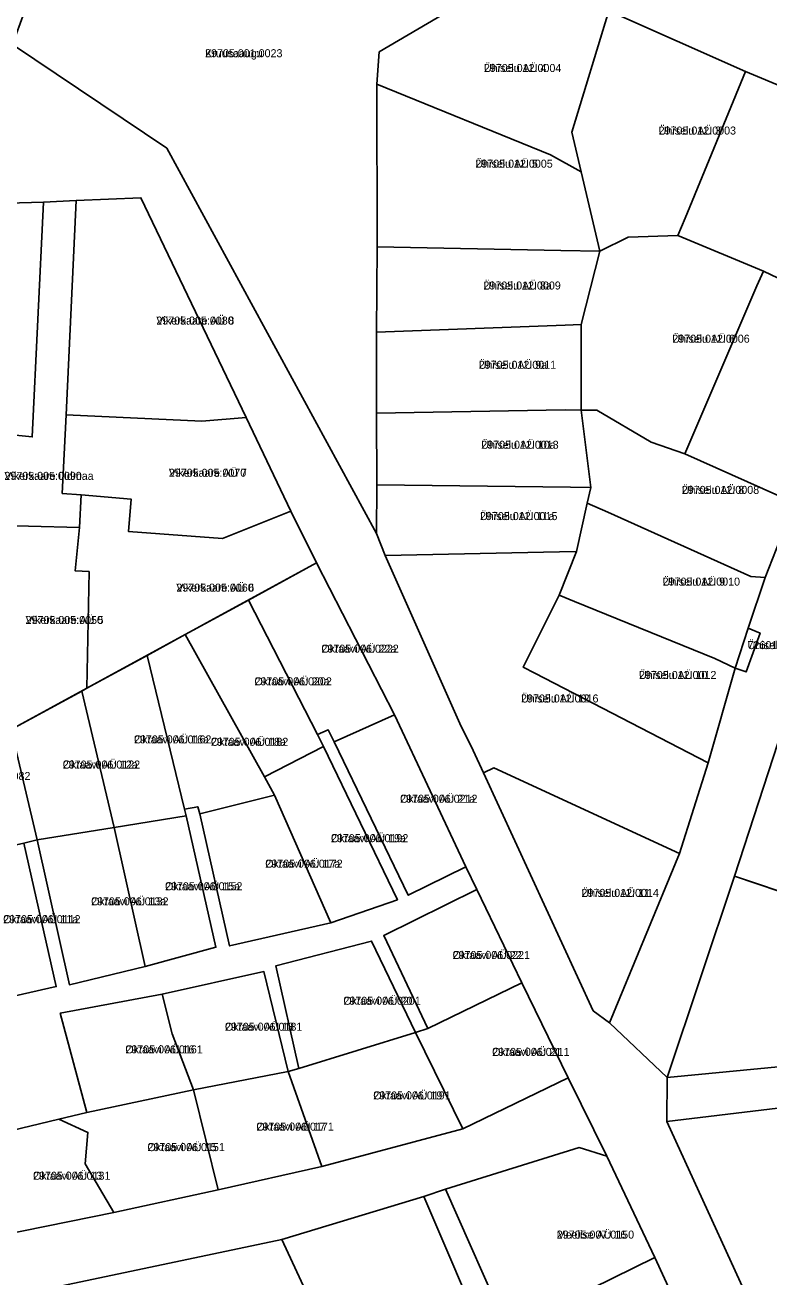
# Model space of a CAD drawing. Extents: x 504287 to 537970, y 6539941 to 6586214.
# Drawn here: x 519134.4 to 519273.8, y 6563201.2 to 6563435.8 of the extents above; entities that cross this region are included whole.
import ezdxf

# ---------------------------------------------------------------- set-up
doc = ezdxf.new("R2010")
doc.units = 0
for name, color, linetype in [('L_AADRESS', 7, 'Continuous'), ('PIIR', 7, 'Continuous'), ('TUNNUS', 7, 'Continuous')]:
    doc.layers.add(name, color=color, linetype=linetype)

msp = doc.modelspace()

# ---------------------------------------------------------------- linework, layer by layer
at = {"layer": 'PIIR'}
for points in [[(519140.05, 6563476.97), (519153.68, 6563480.42), (519218.45, 6563486.02), (519326.38, 6563519.01), (519226.15, 6563445.74), (519200.78, 6563430.75), (519200.34, 6563424.73), (519200.43, 6563394.25), (519200.26, 6563378.22), (519200.3, 6563363.09), (519200.34, 6563349.64), (519200.31, 6563340.52), (519160.99, 6563412.72), (519132.07, 6563432.14), (519134.26, 6563438.15), (519138.11, 6563452.64)], [(519350.47, 6563485.2), (519381, 6563460.99), (519434.83, 6563428.79), (519416.35, 6563420.15), (519412.28, 6563418.89), (519380.79, 6563408.69), (519350.37, 6563399.28), (519345.34, 6563397.59), (519329.1, 6563391.84), (519322.55, 6563399.61), (519317.71, 6563405.41), (519293.21, 6563417.16), (519269.41, 6563427.1), (519243.82, 6563438.48), (519226.15, 6563445.74), (519326.38, 6563519.01)], [(519226.15, 6563445.74), (519241.86, 6563439.37), (519243.82, 6563438.48), (519236.91, 6563415.74), (519238.66, 6563408.27), (519232.9, 6563411.48), (519200.34, 6563424.73), (519200.78, 6563430.75)], [(519243.82, 6563438.48), (519269.41, 6563427.1), (519258.11, 6563399.62), (519256.76, 6563396.34), (519247.47, 6563396.06), (519242.12, 6563393.41), (519238.66, 6563408.27), (519236.91, 6563415.74)], [(519269.41, 6563427.1), (519293.21, 6563417.16), (519281.99, 6563388.88), (519280.8, 6563385.86), (519272.83, 6563389.69), (519256.76, 6563396.34), (519258.11, 6563399.62)], [(519200.34, 6563424.73), (519232.9, 6563411.48), (519238.66, 6563408.27), (519242.12, 6563393.41), (519234.84, 6563393.56), (519200.43, 6563394.25)], [(519116.74, 6563364.03), (519113.68, 6563364.22), (519114.8, 6563373.92), (519100.63, 6563375.97), (519128.79, 6563402.34), (519137.88, 6563402.61), (519135.78, 6563358.63), (519118.22, 6563360.41)], [(519116.13, 6563342.47), (519116.63, 6563346.75), (519118.22, 6563360.41), (519135.78, 6563358.63), (519137.88, 6563402.61), (519144.03, 6563402.9), (519142.15, 6563362.74), (519141.4, 6563348.02), (519144.96, 6563347.74), (519144.6, 6563341.63), (519125.43, 6563342.12)], [(519144.03, 6563402.9), (519156.12, 6563403.42), (519175.89, 6563362.25), (519167.56, 6563361.55), (519142.15, 6563362.74)], [(519243.96, 6563248.8), (519257.06, 6563280.53), (519262.44, 6563297.56), (519267.48, 6563315.28), (519269.57, 6563314.59), (519272.18, 6563321.86), (519269.95, 6563322.75), (519273.12, 6563332.24), (519278.63, 6563346.24), (519294.26, 6563375.39), (519296.93, 6563378.08), (519299.61, 6563380.78), (519322.55, 6563399.61), (519329.1, 6563391.84), (519318.65, 6563382.18), (519307.91, 6563372.29), (519305.41, 6563369.96), (519294.2, 6563350.93), (519291.63, 6563346.35), (519288.21, 6563340.08), (519278.22, 6563309.66), (519267.39, 6563276.29), (519254.76, 6563238.59)], [(519242.12, 6563393.41), (519247.47, 6563396.06), (519256.76, 6563396.34), (519272.83, 6563389.69), (519271.59, 6563386.95), (519258.09, 6563355.42), (519251.76, 6563357.61), (519241.56, 6563363.61), (519238.62, 6563363.64), (519238.64, 6563379.67)], [(519200.43, 6563394.25), (519234.84, 6563393.56), (519242.12, 6563393.41), (519238.64, 6563379.67), (519235.64, 6563379.56), (519200.26, 6563378.22)], [(519272.83, 6563389.69), (519280.8, 6563385.86), (519296.93, 6563378.08), (519294.26, 6563375.39), (519278.63, 6563346.24), (519258.09, 6563355.42), (519271.59, 6563386.95)], [(519200.26, 6563378.22), (519235.64, 6563379.56), (519238.64, 6563379.67), (519238.62, 6563363.64), (519235.67, 6563363.68), (519200.3, 6563363.09)], [(519154.28, 6563346.97), (519144.96, 6563347.74), (519141.4, 6563348.02), (519142.15, 6563362.74), (519167.56, 6563361.55), (519175.89, 6563362.25), (519184.24, 6563344.73), (519171.4, 6563339.55), (519153.79, 6563340.9)], [(519200.3, 6563363.09), (519235.67, 6563363.68), (519238.62, 6563363.64), (519240.44, 6563349.13), (519236.65, 6563349.18), (519200.34, 6563349.64)], [(519238.62, 6563363.64), (519241.56, 6563363.61), (519251.76, 6563357.61), (519258.09, 6563355.42), (519278.63, 6563346.24), (519273.12, 6563332.24), (519270.45, 6563332.44), (519243.61, 6563344.49), (519239.78, 6563346.21), (519240.44, 6563349.13)], [(519146.43, 6563333.37), (519143.81, 6563333.54), (519144.6, 6563341.63), (519144.96, 6563347.74), (519154.28, 6563346.97), (519153.79, 6563340.9), (519171.4, 6563339.55), (519184.24, 6563344.73), (519189.04, 6563335.01), (519146.02, 6563311.51)], [(519200.34, 6563349.64), (519236.65, 6563349.18), (519240.44, 6563349.13), (519239.78, 6563346.21), (519237.75, 6563337.17), (519234.58, 6563337.1), (519201.92, 6563336.41), (519200.31, 6563340.52)], [(519239.78, 6563346.21), (519243.61, 6563344.49), (519270.45, 6563332.44), (519273.12, 6563332.24), (519269.95, 6563322.75), (519267.48, 6563315.28), (519263.7, 6563317.11), (519237.42, 6563327.76), (519234.49, 6563328.95), (519237.75, 6563337.17)], [(519122.62, 6563308.55), (519125.43, 6563342.12), (519144.6, 6563341.63), (519143.81, 6563333.54), (519146.43, 6563333.37), (519146.02, 6563311.51), (519131.85, 6563303.77)], [(519201.92, 6563336.41), (519234.58, 6563337.1), (519237.75, 6563337.17), (519234.49, 6563328.95), (519227.8, 6563315.45), (519229.95, 6563314.34), (519262.44, 6563297.56), (519257.06, 6563280.53), (519222.29, 6563296.59), (519220.33, 6563295.68), (519218.38, 6563299.83), (519215.93, 6563304.93)], [(519189.04, 6563335.01), (519203.64, 6563306.54), (519192.38, 6563301.49), (519191.24, 6563303.72), (519189.23, 6563302.82), (519176.29, 6563328.04)], [(519234.49, 6563328.95), (519237.42, 6563327.76), (519263.7, 6563317.11), (519267.48, 6563315.28), (519262.44, 6563297.56), (519229.95, 6563314.34), (519227.8, 6563315.45)], [(519176.29, 6563328.04), (519189.23, 6563302.82), (519190.38, 6563300.59), (519179.29, 6563294.91), (519164.45, 6563321.58)], [(519267.48, 6563315.28), (519269.95, 6563322.75), (519272.18, 6563321.86), (519269.57, 6563314.59)], [(519166.79, 6563289.32), (519164.28, 6563288.84), (519157.29, 6563317.67), (519164.45, 6563321.58), (519179.29, 6563294.91), (519181.2, 6563291.47), (519167.18, 6563287.98)], [(519145.06, 6563310.99), (519146.02, 6563311.51), (519157.29, 6563317.67), (519164.28, 6563288.84), (519164.62, 6563287.6), (519151.13, 6563285.44)], [(519131.85, 6563303.77), (519145.06, 6563310.99), (519151.13, 6563285.44), (519136.69, 6563283.13)], [(519121.14, 6563309.32), (519122.62, 6563308.55), (519131.85, 6563303.77), (519136.69, 6563283.13), (519134.19, 6563282.46), (519120.36, 6563279.43), (519105.18, 6563291.09)], [(519314.69, 6563297.36), (519307.34, 6563281.57), (519292.55, 6563267.85), (519267.39, 6563276.29), (519278.22, 6563309.66)], [(519203.64, 6563306.54), (519217.05, 6563278.05), (519206.23, 6563272.72), (519192.38, 6563301.49)], [(519181.2, 6563291.47), (519179.29, 6563294.91), (519190.38, 6563300.59), (519204.2, 6563271.88), (519191.7, 6563267.57)], [(519220.33, 6563295.68), (519222.29, 6563296.59), (519257.06, 6563280.53), (519243.96, 6563248.8), (519240.88, 6563251.08)], [(519167.18, 6563287.98), (519181.2, 6563291.47), (519191.7, 6563267.57), (519172.75, 6563263.22)], [(519151.13, 6563285.44), (519164.62, 6563287.6), (519170.18, 6563262.97), (519156.94, 6563259.34)], [(519136.69, 6563283.13), (519151.13, 6563285.44), (519156.94, 6563259.34), (519142.74, 6563255.94)], [(519120.36, 6563279.43), (519134.19, 6563282.46), (519140.28, 6563255.61), (519126.2, 6563252.44)], [(519267.39, 6563276.29), (519292.51, 6563267.78), (519299.01, 6563242.84), (519254.76, 6563238.59)], [(519201.65, 6563265.15), (519219.07, 6563273.77), (519227.54, 6563256.3), (519209.93, 6563247.77)], [(519181.43, 6563259.52), (519199.36, 6563264.14), (519207.57, 6563247), (519185.76, 6563240.25)], [(519162.01, 6563246.75), (519160.12, 6563254.19), (519179.2, 6563258.42), (519183.74, 6563239.71), (519166.02, 6563236.24)], [(519207.57, 6563247), (519209.93, 6563247.77), (519227.54, 6563256.3), (519236.2, 6563238.48), (519216.47, 6563228.93)], [(519141.01, 6563250.64), (519160.12, 6563254.19), (519162.01, 6563246.75), (519166.02, 6563236.24), (519145.99, 6563231.98)], [(519183.74, 6563239.71), (519185.76, 6563240.25), (519207.57, 6563247), (519216.47, 6563228.93), (519190.06, 6563221.91)], [(519166.02, 6563236.24), (519183.74, 6563239.71), (519190.06, 6563221.91), (519170.59, 6563217.51)], [(519236.2, 6563238.48), (519243.47, 6563223.81), (519238.26, 6563225.44), (519213.24, 6563217.67), (519209.13, 6563216.28), (519182.57, 6563208.19), (519141.33, 6563199.52), (519136.15, 6563198.16), (519102.94, 6563190.91), (519097.15, 6563189.57), (519075.1, 6563172.56), (519071.2, 6563169.74), (519047.83, 6563153.98), (519019.15, 6563136.44), (519010.92, 6563141.43), (519070.28, 6563181.56), (519092.24, 6563203.65), (519125.45, 6563208.08), (519151.08, 6563213.3), (519170.59, 6563217.51), (519190.06, 6563221.91), (519216.47, 6563228.93)], [(519145.7, 6563222.39), (519146.21, 6563228.27), (519140.76, 6563230.74), (519145.99, 6563231.98), (519166.02, 6563236.24), (519170.59, 6563217.51), (519151.08, 6563213.3)], [(519293.15, 6563234.92), (519298.22, 6563198.28), (519274.24, 6563187.6), (519254.72, 6563230.35)], [(519123.65, 6563226.94), (519130.13, 6563228.2), (519140.76, 6563230.74), (519146.21, 6563228.27), (519145.7, 6563222.39), (519151.08, 6563213.3), (519125.45, 6563208.08)], [(519213.24, 6563217.67), (519238.26, 6563225.44), (519243.47, 6563223.81), (519252.43, 6563204.86), (519224.92, 6563191.31)], [(519188.58, 6563195.18), (519182.57, 6563208.19), (519209.13, 6563216.28), (519221.29, 6563187.94), (519197.09, 6563176.65)], [(519195.93, 6563150.95), (519193.44, 6563158.03), (519188.13, 6563172.69), (519197.09, 6563176.65), (519221.29, 6563187.94), (519209.13, 6563216.28), (519213.24, 6563217.67), (519224.92, 6563191.31), (519233.88, 6563168.84), (519205.14, 6563155.29)], [(519142.12, 6563196.85), (519141.33, 6563199.52), (519182.57, 6563208.19), (519188.58, 6563195.18), (519151.01, 6563177.45)], [(519224.92, 6563191.31), (519252.43, 6563204.86), (519262.87, 6563182.15), (519233.88, 6563168.84)]]:
    msp.add_lwpolyline(points, close=True, dxfattribs=at)
for points in [[(519132.07, 6563432.14), (519160.99, 6563412.72), (519200.31, 6563340.52), (519201.92, 6563336.41), (519215.93, 6563304.93), (519218.38, 6563299.83), (519220.33, 6563295.68), (519240.88, 6563251.08), (519243.96, 6563248.8), (519254.76, 6563238.59), (519254.72, 6563230.35), (519274.24, 6563187.6)], [(519262.87, 6563182.15), (519252.43, 6563204.86), (519243.47, 6563223.81), (519236.2, 6563238.48), (519227.54, 6563256.3), (519219.07, 6563273.77), (519217.05, 6563278.05), (519203.64, 6563306.54), (519189.04, 6563335.01), (519184.24, 6563344.73), (519175.89, 6563362.25), (519156.12, 6563403.42), (519144.03, 6563402.9), (519137.88, 6563402.61), (519128.79, 6563402.34)], [(519126.2, 6563252.44), (519140.28, 6563255.61), (519134.19, 6563282.46), (519136.69, 6563283.13), (519142.74, 6563255.94), (519156.94, 6563259.34), (519170.18, 6563262.97), (519164.62, 6563287.6), (519164.28, 6563288.84), (519166.79, 6563289.32), (519167.18, 6563287.98), (519172.75, 6563263.22), (519191.7, 6563267.57), (519204.2, 6563271.88), (519190.38, 6563300.59), (519189.23, 6563302.82), (519191.24, 6563303.72), (519192.38, 6563301.49), (519206.23, 6563272.72), (519217.05, 6563278.05), (519219.07, 6563273.77), (519201.65, 6563265.15), (519209.93, 6563247.77), (519207.57, 6563247), (519199.36, 6563264.14), (519181.43, 6563259.52), (519185.76, 6563240.25), (519183.74, 6563239.71), (519179.2, 6563258.42), (519160.12, 6563254.19), (519141.01, 6563250.64), (519145.99, 6563231.98), (519140.76, 6563230.74), (519130.13, 6563228.2)], [(519293.15, 6563234.92), (519254.72, 6563230.35), (519254.76, 6563238.59), (519299.01, 6563242.84)]]:
    msp.add_lwpolyline(points, dxfattribs=at)

# ---------------------------------------------------------------- texts
at = {"layer": 'L_AADRESS'}
for s, p in [('Kruusaaugu', (519168.16, 6563429.77)), ('Ühiselu AÜ 4', (519220.42, 6563427)), ('Ühiselu AÜ 3', (519253.16, 6563415.28)), ('Ühiselu AÜ 5', (519218.81, 6563409.07)), ('Ühiselu AÜ 8a', (519220.32, 6563386.24)), ('Vikerkaare AÜ 8', (519159.02, 6563379.67)), ('Ühiselu AÜ 6', (519255.72, 6563376.27)), ('Ühiselu AÜ 9a', (519219.45, 6563371.38)), ('Ühiselu AÜ 10a', (519219.92, 6563356.4)), ('Vikerkaare AÜ 7', (519161.37, 6563351.15)), ('Vikerkaare üldmaa', (519130.55, 6563350.57)), ('Ühiselu AÜ 8', (519257.5, 6563347.94)), ('Ühiselu AÜ 11a', (519219.69, 6563343.03)), ('Vikerkaare AÜ 6', (519162.77, 6563329.62)), ('Ühiselu AÜ 9', (519253.91, 6563330.75)), ('Vikerkaare AÜ 5', (519134.52, 6563323.56)), ('Oktaavi AÜ 22a', (519189.96, 6563318.18)), ('Ühiselu AÜ 9b', (519269.83, 6563318.85)), ('Ühiselu AÜ 10', (519249.48, 6563313.25)), ('Oktaavi AÜ 20a', (519177.42, 6563312.06)), ('Ühiselu AÜ 12', (519227.38, 6563308.85)), ('Oktaavi AÜ 16a', (519154.84, 6563301.18)), ('Oktaavi AÜ 18a', (519169.25, 6563300.73)), ('Oktaavi AÜ 12a', (519141.49, 6563296.47)), ('Oktaavi AÜ 21a', (519204.71, 6563290.06)), ('Oktaavi AÜ 19a', (519191.75, 6563282.67)), ('Oktaavi AÜ 17a', (519179.44, 6563277.89)), ('Oktaavi AÜ 15a', (519160.66, 6563273.66)), ('Oktaavi AÜ 13a', (519146.81, 6563270.83)), ('Ühiselu AÜ 11', (519238.7, 6563272.42)), ('Oktaavi AÜ 11a', (519130.32, 6563267.49)), ('Oktaavi AÜ 22', (519214.55, 6563260.77)), ('Oktaavi AÜ 20', (519194.08, 6563252.2)), ('Oktaavi AÜ 18', (519171.88, 6563247.33)), ('Oktaavi AÜ 16', (519153.22, 6563243.09)), ('Oktaavi AÜ 21', (519221.96, 6563242.62)), ('Oktaavi AÜ 19', (519199.68, 6563234.46)), ('Oktaavi AÜ 17', (519177.78, 6563228.61)), ('Oktaavi AÜ 15', (519157.36, 6563224.77)), ('Oktaavi AÜ 13', (519135.92, 6563219.41)), ('Meelise AÜ 16', (519234.06, 6563208.38))]:
    msp.add_text(s, height=1.5, dxfattribs=at).set_placement(p)
at = {"layer": 'TUNNUS'}
for s, p in [('29705:001:0023', (519168.16, 6563429.77)), ('29705:012:0004', (519220.42, 6563427)), ('29705:012:0003', (519253.16, 6563415.28)), ('29705:012:0005', (519218.81, 6563409.07)), ('29705:012:0009', (519220.32, 6563386.24)), ('29705:005:0080', (519159.02, 6563379.67)), ('29705:012:0006', (519255.72, 6563376.27)), ('29705:012:0011', (519219.45, 6563371.38)), ('29705:012:0013', (519219.92, 6563356.4)), ('29705:005:0070', (519161.37, 6563351.15)), ('29705:005:0090', (519130.55, 6563350.57)), ('29705:012:0008', (519257.5, 6563347.94)), ('29705:012:0015', (519219.69, 6563343.03)), ('29705:012:0010', (519253.91, 6563330.75)), ('29705:005:0060', (519162.77, 6563329.62)), ('29705:005:0050', (519134.52, 6563323.56)), ('29705:006:0222', (519189.96, 6563318.18)), ('72601:001:0994', (519269.83, 6563318.85)), ('29705:012:0012', (519249.48, 6563313.25)), ('29705:006:0202', (519177.42, 6563312.06)), ('29705:012:0016', (519227.38, 6563308.85)), ('29705:006:0162', (519154.84, 6563301.18)), ('29705:006:0182', (519169.25, 6563300.73)), ('29705:006:0122', (519141.49, 6563296.47)), ('29705:006:0082', (519120.93, 6563294.32)), ('29705:006:0212', (519204.71, 6563290.06)), ('29705:006:0192', (519191.75, 6563282.67)), ('29705:006:0172', (519179.44, 6563277.89)), ('29705:006:0152', (519160.66, 6563273.66)), ('29705:012:0014', (519238.7, 6563272.42)), ('29705:006:0132', (519146.81, 6563270.83)), ('29705:006:0112', (519130.32, 6563267.49)), ('29705:006:0221', (519214.55, 6563260.77)), ('29705:006:0201', (519194.08, 6563252.2)), ('29705:006:0181', (519171.88, 6563247.33)), ('29705:006:0161', (519153.22, 6563243.09)), ('29705:006:0211', (519221.96, 6563242.62)), ('29705:006:0191', (519199.68, 6563234.46)), ('29705:006:0171', (519177.78, 6563228.61)), ('29705:006:0151', (519157.36, 6563224.77)), ('29705:006:0131', (519135.92, 6563219.41)), ('29705:007:0150', (519234.06, 6563208.38))]:
    msp.add_text(s, height=1.5, dxfattribs=at).set_placement(p)

doc.saveas('drawing.dxf')
